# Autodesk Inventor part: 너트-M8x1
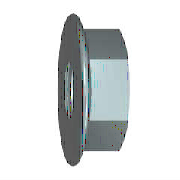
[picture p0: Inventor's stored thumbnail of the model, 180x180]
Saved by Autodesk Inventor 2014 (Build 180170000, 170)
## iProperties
Created: 2015-12
Part Number: 너트-M8x1
Material: 스테인레스 스틸
Description: 플랜지붙이 6각 너트 - 일반 스레드
Document SubType Name: Modeling
Standard: ISO 4161
Designer: mdu
Standard Revision: 2판 1999-03-15
Standards Organization: ISO
Language: ko-KR
Size Designation: M8
Categories: <MemberInstance><Categories><Category DisplayName="조임쇠" InternalName="e4da775c-781d-43d5-af7c-5136215cf5a6" Mnemonic="FSTN"><Category DisplayName="너트" InternalN
Density: 7.87 g/cm^3
Appearance: 노란색
Mass: 8.79821 g
Surface Area: 8.90186 cm^2
Volume: 1.11794 cm^3
Author: mdu
IsCustomPart: 1
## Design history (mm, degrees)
sketch "스케치1"
  geometry: L1 (-1.844, 0)-(9.641, 0) reference; L2 (3.107, 6.5)-(2.288, 8.257); L3 (3.107, 6.5)-(8, 6.5); L4 (8, 6.5)-(8, 0); L5 (3.107, 6.5)-(3.107, 0); L6 (0, -1.835)-(0, 11.01) reference; A1 r 1.2 centre (1.2, 7.75) between (2.288, 8.257) and (0, 7.75); 1 further point
  constraints: 8 end point, 3 point on line, 2 perpendicular, 2 point on circle, 2 tangent, 1 centre point, 1 parallel
  dimensions: "d2" = 13 diameter of L3 L1 (= SW); "d4" = 17.9 dimension on A1 L1 (= LADI); "d5" = 1.2 radius of A1 (= PHH); "d15" = 8 distance between parallel lines of L4 L6 (= KOH); "d16" = 25 deg angle of L6 L2 (= KEWI)
revolve "링" sketch "스케치1" stored, may be unused: angle "d8" = 90 deg
sketch "스케치2"
  geometry: L1 (-6.5, -3.753)-(-6.5, 3.753); L2 (-6.5, 3.753)-(0, 7.506); L3 (0, 7.506)-(6.5, 3.753); L4 (6.5, 3.753)-(6.5, -3.753); L5 (6.5, -3.753)-(0, -7.506); L6 (0, -7.506)-(-6.5, -3.753); C1 r 4.9 at (0, 0); C2 r 7.75 at (0, 0) reference; 1 further point
  constraints: 12 end point, 1 centre point, 1 coincident, 1 vertical, 11 other
  dimensions: "d6" = 15.01111 distance of L5.end L2.end (= 1.1547 x SW)
extrude "본체" join sketch "스케치2" distance "d7" = 8 (= KOH); taper "d9" = 0 deg
sketch "스케치3"
  geometry: L1 (2.638, 7.506)-(8, 7.506) reference; L2 (8, 3.753)-(8, 7.506) reference; L3 (0, -7.75)-(0, 7.75) reference; L4 (-1.6, 0)-(9.6, 0) reference; L5 (7.419, 7.506)-(8, 6.5)
  constraints: 2 end point, 2 point on line
  dimensions: "d10" = 30 deg angle of L2 L5 (= ANG1); "d11" = 13 diameter of L5.end L4 (= SW0)
revolve "모따기1" sketch "스케치3" stored, may be unused: angle "d24" = 90 deg
sketch "스케치4"
  geometry: C1 r 7.75 at (0, 0) reference; 1 further point
  constraints: 1 coincident
hole "스레드" sketch "스케치4" at (0, 0) diameter "d25" = 6.647; stored, may be unused: countersink angle "d29" = 82 deg, drill point angle "d31" = 118 deg; dims "d26" = 6, "d27" = 4, "d28" = 2, "d30" = 8
workaxis "Work Axis1"
workplane "Work Plane1"
body "Solid1"
chamfer "모따기2" distance "d12" = 0.67658 (= -0.5 x GD1 + 0.5 x NND); stored, may be unused: angle "d13" = 30 deg, second distance "d46" = 0.67658 (= -0.5 x GD1 + 0.5 x NND)
chamfer "모따기3" distance "d51" = 0.67658 (= -0.5 x GD1 + 0.5 x NND); stored, may be unused: second distance "d52" = 2, angle "d53" = 45 deg
other parameters: "ANG1" = 30 deg [user parameter; used in 1 equation term], "KEWI" = 25 deg [user parameter; used in 1 equation term], "NND" = 8 [user parameter; used in 4 equation terms], "LADI" = 17.9 [user parameter; used in 2 equation terms], "SW" = 13 [user parameter; used in 3 equation terms], "PHH" = 1.2 [user parameter; used in 3 equation terms], "KOH" = 8 (= NND) [user parameter; used in 2 equation terms], "SW0" = 13 [user parameter; used in 1 equation term], "GD1" = 6.64684 (computed from THREADDIA, PTC, TOA) [user parameter; used in 3 equation terms], "d1" = 17.9 (= LADI), "d3" = 1.2 (= PHH), "d45" = 0, "d47" = 0, "d49" = 0, "d54" = 0, "GUL" = 0.67658 (= 0.541266 x PTC) [user parameter], "TPU" = 8 (computed from PTC) [user parameter], "RR" = 1.2 (= PHH) [user parameter], "THREADDIA" = 8 [user parameter; used in 1 equation term], "TOA" = 30 deg [user parameter; used in 1 equation term], "PTC" = 1.25 [user parameter; used in 4 equation terms], "GAL" = 0.67658 (= 0.541266 x PTC) [user parameter], "E0" = 15.015 (= 1.155 x SW) [user parameter]
